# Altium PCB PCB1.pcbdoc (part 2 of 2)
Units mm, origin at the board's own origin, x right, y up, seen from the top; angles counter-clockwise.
Board outline 376.79 x 262.39 mm, 2 copper layers (Top Layer, Bottom Layer), stack 1.58 mm thick; 505 components, 251 nets, 1356 pads, 0 vias.
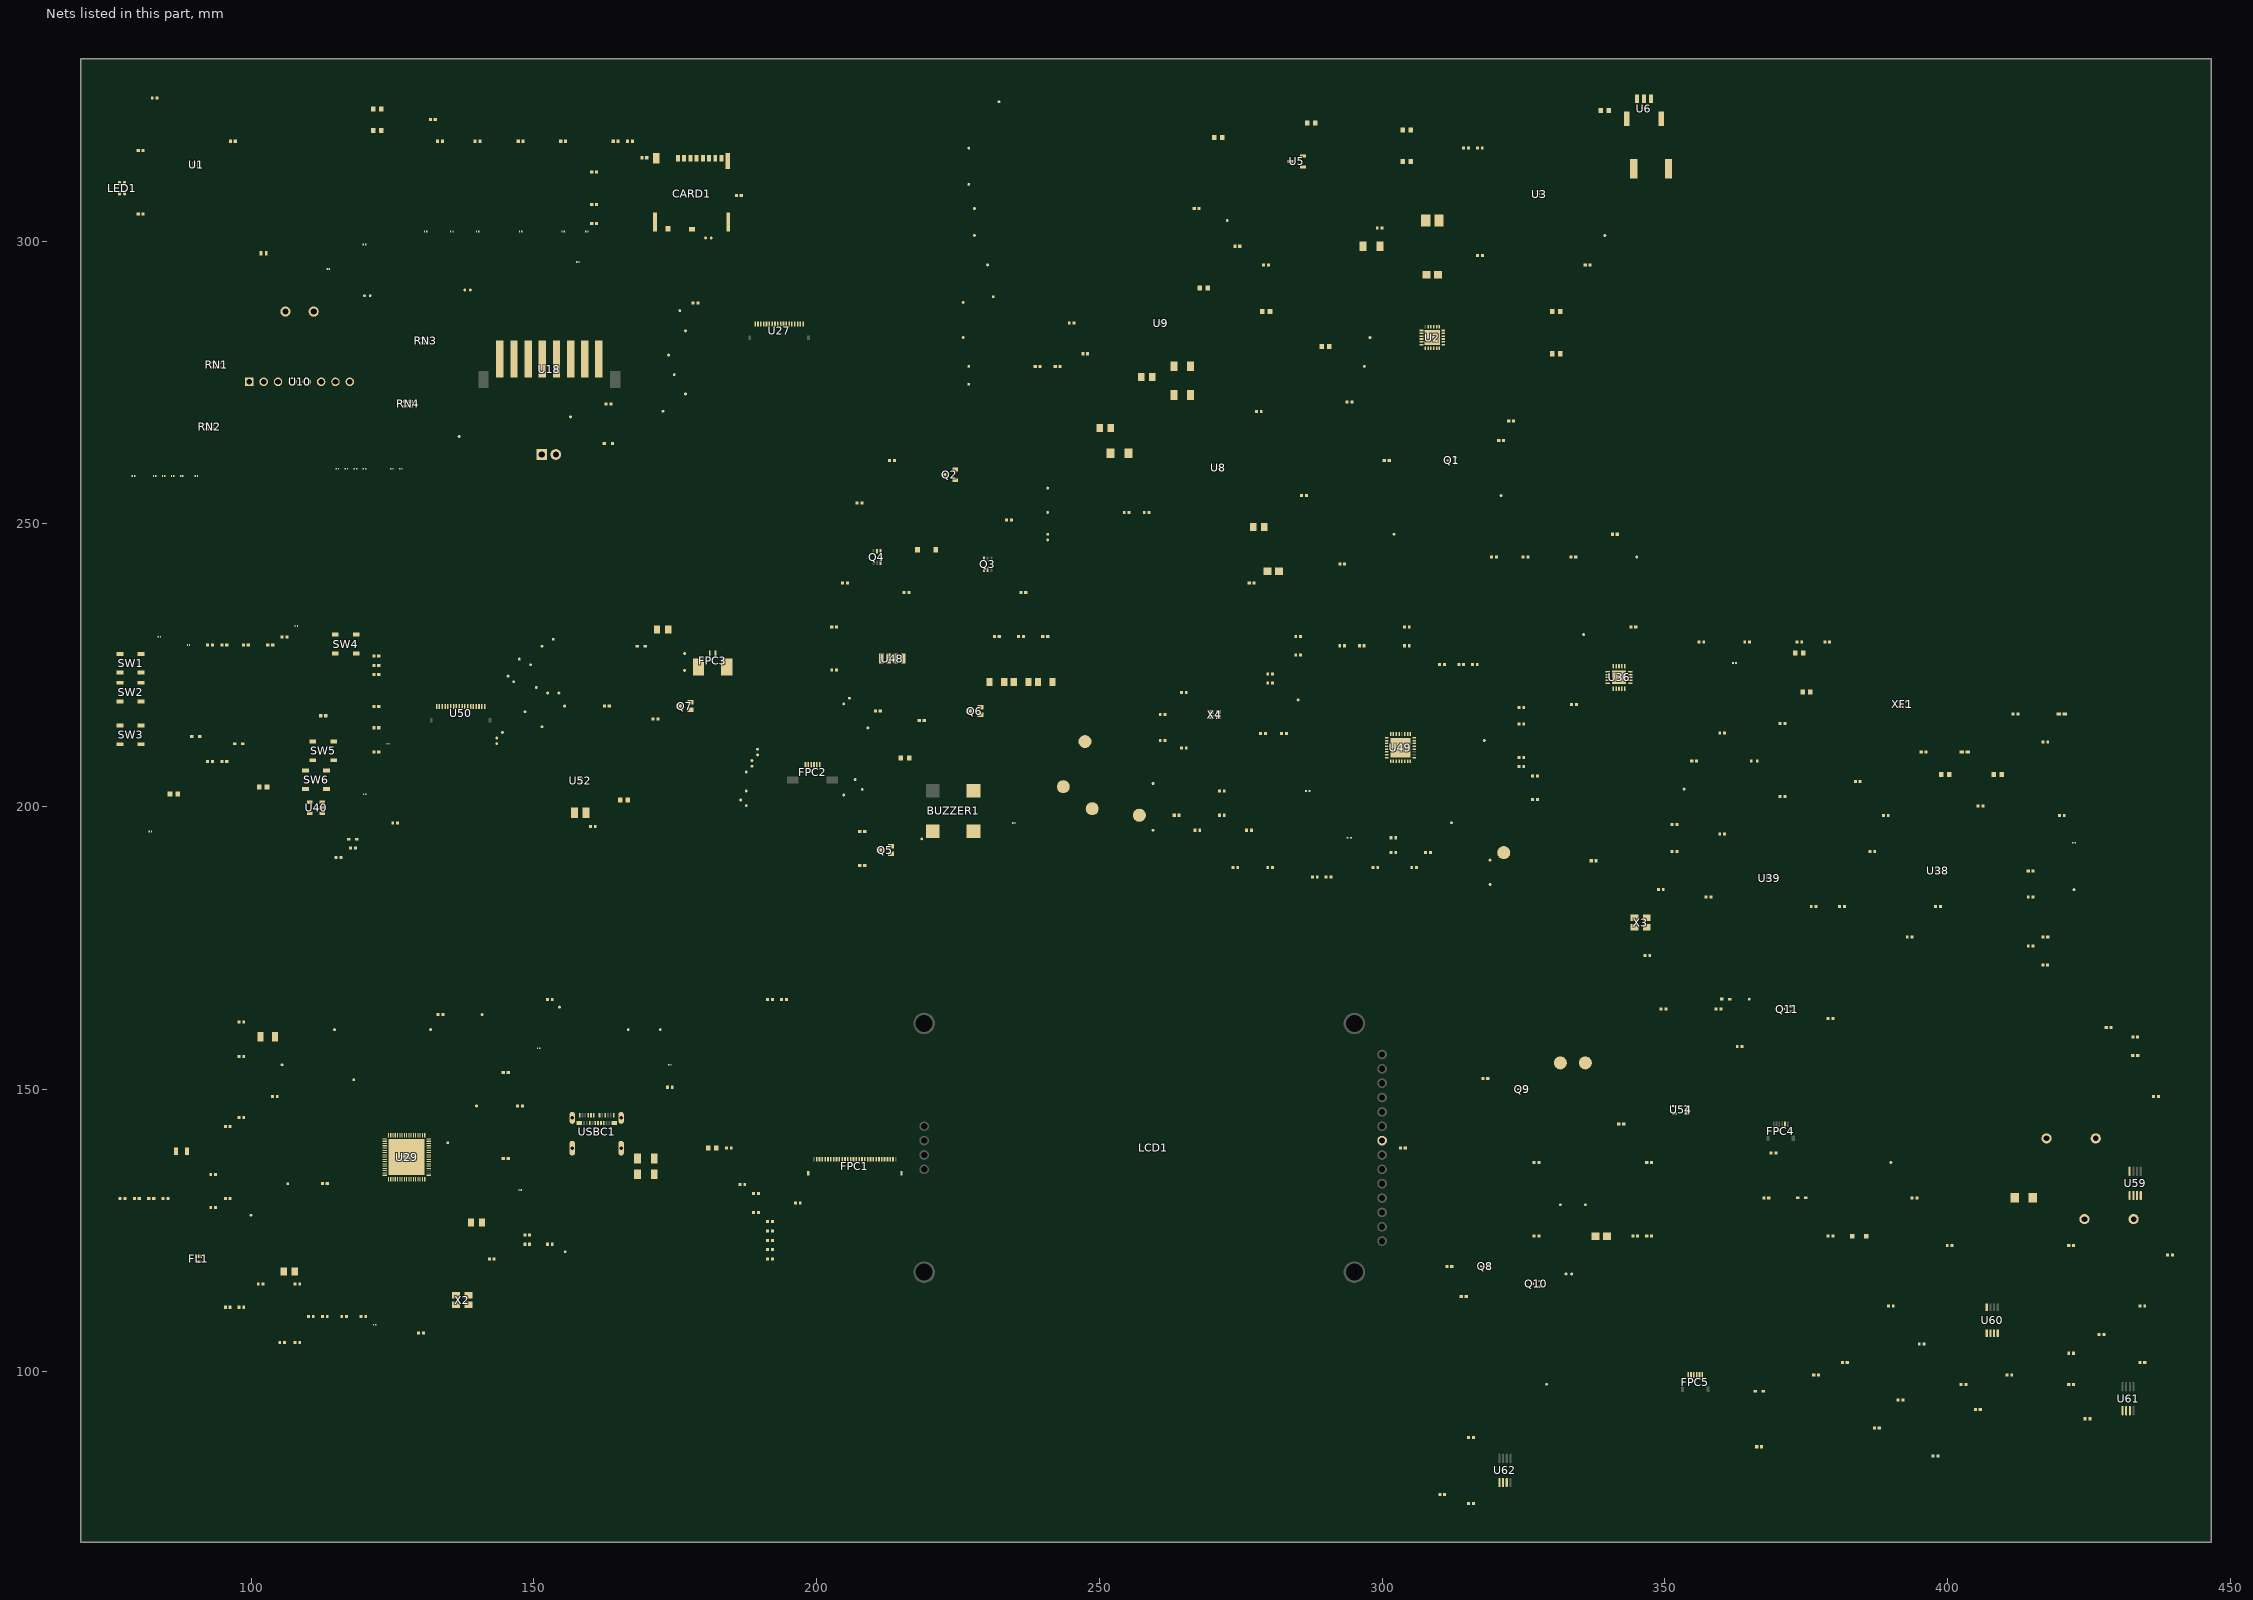
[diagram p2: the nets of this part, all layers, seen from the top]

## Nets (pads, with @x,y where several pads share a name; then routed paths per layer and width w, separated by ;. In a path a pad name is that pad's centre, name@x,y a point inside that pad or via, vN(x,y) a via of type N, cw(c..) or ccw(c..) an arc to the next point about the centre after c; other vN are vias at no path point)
1.65V: R110.1 R111.2 TP64.1 U60.3 U61.3 U62.1 U62.2
3v3: 3v3(2).1 C18.1 C33.1 C34.1 C35.1 C36.2 C37.1 C38.1 C39.1 C42.1 C43.2 C45.2 C46.2 C50.1 C51.2 C61.2 C62.2 C63.1 C64.1 C65.1 C66.1 C82.1 C86.2 C89.1 C122.2 C123.2 FPC1.5 FPC1.6 FPC1.7 FPC1.8 FPC1.9 FPC1.10 FPC1.11 FPC1.12 FPC1.15 R2.2 R3.2 R4.2 R12.1 R13.1 R35.2 R36.2 R39.2 R48.2 R49.2 R61.2 R63.2 R65.1 R69.2 R73.2 R75.2 R101.1 R109.1 SW4.1 SW4.2 SW4.4 TP16.1 TP52.1 TP53.1 U27.3 U29.14 U29.30 U29.33 U29.44 U29.45 U29.55 U29.68 U32.2 U36.4 U36.9 U36.11 U36.14 U36.15 U36.18 U38.7 U39.7 U40.5 U49.1 U50.3
$1N10: R1.1 U2.10
$1N11: PG.1 U2.3
$1N13: STAT.1 U2.4
$1N29: Q1.1 R6.1
$1N34: C2.1 U2.21
$1N35: C2.2 U2.19 U2.20 U4.1
$1N47: R9.2 U3.B1
$1N50: R10.2 U2.22 U7.1
$1N66: C11.1 C12.1 U3.B3
$1N69: GPOUT.1 R12.2 U3.A1
$1N75: L1.2 U8.B2
$1N84: L2.2 R14.1 R15.1
$1N85: C19.2 C20.2 C21.2 L3.2 R14.2 R15.2 U9.A1
$1N86: L3.1 R35.1 R36.1
$1N94: Q2.1 Q3.6 R18.1
$1N123: D7.1 Q3.2 Q4.3 Q4.5 R19.2
$2N2: R29.2 U1.A4
$2N3: R30.2 U1.B4
$2N4: R28.1 U1.C4
$2N5: LED1.1 R28.2
$2N6: LED1.2 R30.1
$2N7: LED1.3 R29.1
$2N16: CARD1.1 R31.1
$2N17: CARD1.8 R32.1
$2N18: C23.2 C24.2 CARD1.4 D5.2 R31.2 R32.2 R33.1 R402.2 R0402.2 R404.2 R406.2
$2N23: CARD1.3 R34.2
$2N25: CARD1.5 R403.2
$2N28: CARD1.7 R405.2
$2N30: CARD1.10 R407.1
$2N31: CARD1.2 R408.2
$2N36: C25.1 F1.1 U10.1
$2N40: RN1.2 U10.2
$2N42: RN1.1 U10.3
$2N44: RN2.4 U10.4
$2N46: RN2.3 U10.5
$2N48: RN2.2 U10.6
$2N50: RN2.1 U10.7
$2N57: RN3.3 U18.2
$2N60: RN3.2 U18.4
$2N62: RN3.1 U18.5 U35.1
$2N64: RN4.4 U18.6 UARTRX.1
$2N66: I2C_SDA.1@156.462,268.906 RN4.3 U18.7
$2N68: I2C_SCL2.1 RN4.2 U18.8
$2N70: RN4.1 U19.1
$2N72: RN4.8 U24.2
$2N88: R23.2 U27.7
$2N95: R24.1 U28.1
$3N6: R37.2 U29.20
$3N41: C27.2 U29.4 X1.2
$3N43: C26.2 U29.3 X1.1
$3N47: U29.35 X2.1
$3N48: U29.34 X2.3
$3N52: L5.1 U29.43
$3N60: R41.1 U29.65
$3N81: C31.1 L4.2 U29.31
$3N85: C32.1 FL1.1 L4.1
$3N96: C40.2 C41.1 U29.13
$3N101: C44.2 L5.2 U29.41
$3N106: R42.1 USBC1.A5
$3N108: R43.1 USBC1.B5
$4N10: C52.1 FPC1.17
$4N12: C53.1 FPC1.18
$4N13: C53.2 C54.2 FPC1.19
$4N14: C54.1 FPC1.20
$4N15: C55.1 FPC1.21
$4N16: C55.2 FPC1.22
$4N17: C56.1 C57.1 C58.1 C59.1 C60.2
$4N18: C56.2 FPC1.23
$4N19: C57.2 FPC1.24
$4N20: C58.2 FPC1.25
$4N21: C59.2 FPC1.26
$4N22: C60.1 FPC1.27
$4N26: LCD1.8 R50.2
$5N8: C67.1 U36.5
$5N10: R51.2 U36.6
$5N13: C68.1 U36.8 X3.1
$5N15: C69.2 U36.10 X3.3
$5N18: C70.1 C71.2 U36.12
$5N20: C70.2 XF1.4
$5N21: C71.1 C72.1 U36.13
$5N22: C72.2 XF1.3
$5N24: R52.1 U36.17
$5N27: L7.1 XF1.1
$5N28: C73.1 L7.2 U37.1
$5N30: C74.2 R53.2 U37.2
$5N36: R54.1 U38.3
$5N37: C75.1 R54.2 R55.2
$5N39: C76.1 L8.2 R55.1
$5N41: L8.1 U39.5
$5N42: R56.1 U38.5
$5N43: C77.1 L9.2 R56.2
$5N45: C78.1 L9.1 R57.1
$5N47: C79.2 L10.2 R57.2
$5N49: L10.1 U39.3
$5N50: R58.1 U38.2
$5N51: C80.1 L11.2 R58.2
$5N53: C81.2 L11.1 U39.2
$5N58: C83.1 L12.2 L13.2 U39.4
$5N61: C84.2 L13.1 R59.1
$5N65: C86.1 U39.6 U39.9
$6N1: R60.1 U40.1
$6N4: R62.1 U40.2
$6N5: D10.1 R62.2 R63.1 R67.1 SW2.4 U41.2
$6N6: C87.2 U41.1
$6N8: C88.2 U42.1
$6N13: U40.4 U43.1
$6N14: R64.2 U43.2
$6N17: D9.1 R60.2 R61.1 R66.1 SW1.4 U42.2
$6N22: D11.2 R68.1 R69.1 SW3.4
$6N25: D12.1 R70.1 R71.1 SW4.3
$6N31: D13.2 R72.1 R73.1 SW5.4
$6N34: D14.2 R74.1 R75.1 SW6.1
$7N2: FPC2.2 R77.2 TP20.1
$7N3: Q5.1 R77.1 R78.2
$7N5: BUZZER1.2 Q5.3 TP21.1
$7N6: BUZZER1.1 R79.1
$7N8: BUZZER1.3 CN1.1 CN2.1 FPC2.3 TP22.1 U44.2
$7N11: FPC2.4 R80.2 TP23.1
$7N12: Q6.1 R80.1 R81.2
$7N14: Q6.3 U45.1 U46.1 U47.1
$7N15: R84.1 U47.2
$7N16: R83.1 U46.2
$7N17: R82.1 U45.2
$7N19: FPC2.5 TP24.1 U48.3
$7N24: C90.1 R76.2 U48.2
$8N2: TP26.1 U49.25
$8N10: TP27.1 U49.2
$8N11: C94.2 U49.4 X4.3
$8N12: C95.2 U49.5 X4.4
$8N17: L14.2 U49.13
$8N18: C96.2 C98.1 C100.2 L14.1
$8N19: C96.1 C97.1 C98.2 C101.1 R85.2
$8N22: L15.1 U49.15
$8N23: C102.1 C103.2 C104.2 L15.2
$8N24: C102.2 C103.1 C105.1 C106.1 R86.1
$8N30: TP32.1 U49.17
$8N31: C108.2 C109.1 U49.24
$8N33: C110.2 C111.2 R87.1 R88.1 U49.9 U49.14
$8N37: C112.2 C113.2 U49.11
$8N44: C118.2 C119.2 U49.7
$8N46: C120.2 C121.2 U49.3
$9N8: R89.1 TP38.1 U50.10
$9N9: Q7.1 R89.2 R90.2
$9N12: FPC3.2 Q7.3 TP39.1 U51.2
$9N14: FPC3.1 R92.1 TP40.1 U51.1
$9N27: U52.B1 U52.B2 U53.2
$10N2: Q8.1 R91.2 R93.2
$10N4: Q8.3 Q9.1 Q10.1 R94.1
$10N7: Q9.2 R95.2
$10N9: Q10.3 R96.1
$10N14: R98.2 R99.2 U54.1
$10N20: R100.2 U55.2
$10N22: C129.2 R102.2 R103.1 R106.1 TP63.1 U55.1 U57.1
$10N24: Q11.3 R103.2
$10N27: R104.1 R105.2 U56.1
$10N28: Q11.1 R104.2
$10N33: FPC5.4 R108.1
$10N36: FPC5.2 U58.1
$10N43: C130.2 C131.1 R106.2
$10N44: C131.2 D15DNP1.1 D15DNP.2 R110.2 U59.3
$10N49: C133.2 R111.1 R112.1 U59.2
$10N53: C133.1 R112.2 R113.2 U59.1
$10N55: C134.1 R113.1 R114.1 R115.2
$10N57: C135.2 R114.2 U60.2
$10N59: C135.1 R115.1 R116.1 U60.1
$10N63: C137.2 R116.2 R117.1 R118.2
$10N65: C138.2 R117.2 U61.2
$10N66: C138.1 R118.1 R119.2 U61.1
$10N68: C139.1 R119.1
$10N71: C140.2 R121.1 R122.2 U62.3
A3V3: C128.2 C132.2 C136.2 D15DNP.1 R121.2 U54.5 U59.8 U60.8
ANTENA_DRAW: C85.2 R59.2 TP18.1
BAT: BAT1.1 BAT2.1 C9.1 R8.2 U3.C1 U3.C3 U6.1
BaTbq-xc6206: C6.2 C7.1 C8.1 U2.13 U2.14 U5.3
BaTbq-xc6207: R8.1 U3.C2
BUTTON_BACK: R66.2 U2.12 U29.2
BUTTON_DOWN: R74.2 U29.50
BUTTON_LEFT: R67.2 U29.29
BUTTON_OK: R70.2 TP11.1 U29.5
BUTTON_RIGHT: R68.2 U29.46
BUTTON_UP: R72.2 U29.28
CC1101_CS: U29.61 U36.7
CC1110_G0: R51.1 U29.16
DISPLAY_CS: FPC1.2 R48.1 U29.59
DISPLAY_DI: FPC1.4 U29.39
DISPLAY_RST: FPC1.3 R49.1 U29.38
"drainosfet e1": Q2.3 R16.1
e24mmd: D7.2 Q4.4 R16.2 R17.1
ext3.3v: C14.2 C15.2 D8.2 EXT3V3(2).1 EXT_3V3.1 L1.1 R27.1 R33.2 U8.A1 U18.1
GND: C1.1 C3.1 C4.1 C5.1 C6.1 C7.2 C8.2 C9.2 C10.1 C11.2 C12.2 C14.1 C15.1 C18.2 C19.1 C20.1 C22.2 C23.1 C24.1 C25.2 C26.1 C27.1 C28.1 C29.1 C30.2 C31.2 C32.2 C33.2 C34.2 C35.2 C36.1 C37.2 C38.2 C39.2 C40.1 C41.2 C42.2 C43.1 C44.1 C45.1 C46.1 C47.1 C48.1 C48.2 C49.1 C49.2 C50.2 C51.1 C52.2 C61.1 C62.1 C63.2 C64.2 C65.2 C66.2 C67.2 C68.2 C69.1 C73.2 C74.1 C75.2 C76.2 C77.2 C78.2 C79.1 C80.2 C81.1 C82.2 C83.2 C84.1 C85.1 C87.1 C88.1 C89.2 C90.2 C91.1 C92.1 C93.1 C94.1 C95.1 C99.2 C100.1 C101.2 C104.1 C105.2 C107.2 C108.1 C109.2 C110.1 C111.1 C112.1 C113.1 C114.1 C115.1 C116.1 C117.1 C118.1 C119.1 C120.1 C121.1 C122.1 C123.1 C124.1 C125.1 C126.1 C126.2 C127.1 C127.2 C128.1 C130.1 C132.1 C134.2 C136.1 C137.1 C139.2 C140.1 CARD1.6 CARD1.9 CARD1.11 CN3.1 CN4.1 CN5.1 CN6.1 CN7.1 D1.1 D2.1 D3.1 D4.1 D5.1 D6.1 D8.1 D9.2 D10.2 D11.1 D12.2 D13.1 D14.1 D15DNP1.2 FL1.2 FL1.3 FL1.5 FPC1.16 FPC1.28 FPC1.29 FPC1.31 FPC1.32 FPC2.6 FPC3.3 FPC3.4 FPC5.1 GND1.1 GND2.1 GND3.1 GND4.1 L6.1 L6.2 L12.1 Q1.2 Q5.2 Q6.2 Q7.2 Q8.2 Q10.2 Q11.2 R1.2 R7.2 R9.1 R11.1 R18.2 R19.1 R20.2 R21.1 R22.2 R42.2 R43.2 R44.1 R44.2 R45.1 R45.2 R46.1 R46.2 R47.1 R47.2 R52.2 R53.1 R71.2 R78.1 R81.1 R85.1 R86.2 R87.2 R88.2 R90.1 R93.1 R95.1 R96.2 R97.1 R97.2 R98.1 R100.1 R102.1 R120.1 R120.2 R122.1 SW1.1 SW1.2 SW1.3 SW2.1 SW2.2 SW2.3 SW3.1 SW3.2 SW3.3 SW5.1 SW5.2 SW5.3 SW6.2 SW6.3 SW6.4 TP1.1 TP15.1 TP17.1 TP25.1 TP28.1 TP29.1 TP30.1 TP31.1 TP34.1 TP35.1 TP50.1 TP51.1 TP58.1 TP59.1 TP60.1 TP61.1 U1.A3 U1.B1 U1.B2 U1.B3 U2.2 U2.9 U2.17 U2.18 U2.25 U3.B2 U5.1 U6.3 U6.4 U6.5 U7.2 U10.8 U11.1 U12.1 U13.1 U14.1 U15.1 U16.1 U17.1 U18.3 U19.2 U20.1 U21.1 U22.1 U23.1 U24.1 U25.1 U26.2 U27.5 U27.17 U27.18 U29.26 U29.32 U29.42 U29.69 U30.1 U31.2 U32.1 U33.1 U34.1 U34.2 U36.16 U36.19 U36.21 U38.4 U38.6 U38.9 U40.3 U44.1 U48.1 U48.4 U49.6 U49.12 U49.16 U49.20 U49.21 U49.26 U49.33 U50.5 U50.6 U50.8 U52.C1 U52.C2 U52.C3 U54.2 U54.3 U57.2 U59.4 U60.4 USBC1.0 USBC1.A1 USBC1.A12 USBC1.B1 USBC1.B12 X2.2 X2.4 X3.2 X3.4 X4.1 X4.2 XF1.2
I2C_SCL: R4.1 R25.1 R25.2 U1.C2 U2.5 U3.A3 U29.24
I2C_SDA: I2C_SDA.1@345.048,244.129 R3.1 U1.C1 U2.6 U3.A2 U29.51
iBTN: C129.1 R24.2 R107.1 R108.2 TP45.1 U27.12 U29.48 U50.14
IR_RX: R109.2 TP48.1 U27.15 U29.15 U50.17 U58.2
IR_TX: FPC5.3 IR_TX.1 TP47.1 U27.14 U29.7 U50.16
LCD_LED: U1.A1
LDO_3.3V: C10.2 LDO1.1 LDO2.1 U5.2 U29.1
NET1_N: D-.1 R38.1 U29.52
NET1_P: R39.1 R40.2 TP5.1 U29.53
NET2_N: R38.2 U30.2 USBC1.A7 USBC1.B7
NET2_P: R40.1 U31.1 USBC1.A6 USBC1.B6
NFC_CS: NFC_CS.1 TP33.1 U27.4 U29.40 U49.29 U50.4
NFC_IRQ: TP62.1 U49.27 U56.2
OTG: OTG.1 Q1.3 R5.2 U2.8
PA4: RN2.5 U13.2 U29.19
PA6: RN1.8 U12.2 U29.21
PA7: RN1.7 U17.2 U29.22
PB2: RN2.7 U15.2 U29.27
PB3: RN2.6 U14.2 U29.63
PC0: RN4.7 U23.2 U29.9
PC1: RN4.6 U20.2 U29.10
PC3: RN2.8 U16.2 U29.12
PERIPH_POWER: R13.2 U8.C1 U29.18
PGND: C17.1 C21.1 R21.2 U9.C2
PGND2: C13.1 C16.2 R22.1 U8.C2
PWR_INT: PWR_INT.1 R2.1 U2.7
REGN: R20.1 R26.1 TEMP.1 U6.2
RESET: C30.1 R64.1 R65.2 TP12.1 U1.C3 U29.8
RF_SW_0: U29.25 U38.8 U39.1
RF_SW_1: U36.3 U38.1 U39.8
RFI_N: C106.2 C107.1 U49.23
RFI_P: C97.2 C99.1 U49.22
RFID__CARRED: FPC4.2 R99.1 R101.2 TP4.1 TP49.1 U27.16 U29.57 U50.18 U54.4
RFID_OUT: R91.1 TP2.1 TP42.1 U27.10 U29.47 U50.12
RFID_PULL: R105.1 RFID_PULL.1 TP41.1 TP44.1 U27.9 U29.17 U50.11
SD_CD: D6.2 R406.1 R407.2 U29.58
SD_CS: D1.2 R408.1 U29.60
SPEAKER: FPC5.5 TP3.1 TP46.1 U27.13 U29.6 U50.15
SPI_D_MISO: D4.2 R404.1 R405.1 TP6.1 U29.11
SPI_D_MOSI: C28.2 D2.2 FPC1.14 R34.1 R0402.1 TP9.1 U29.49
SPI_D_SCK: C29.2 D3.2 FPC1.13 R402.1 R403.1 TP10.1 U29.62
SPI_R_MISO: C93.2 R23.1 TP7.1 TP37.1 U29.64 U36.2 U49.32 U50.9
SPI_R_MOSI: C92.2 R41.2 TP8.1 TP43.1 U36.20 U49.31 U50.13
SPI_R_SCK: C91.2 R37.1 R_CLK.1 TP36.1 U27.6 U36.1 U49.30 U50.7
ST25_R_MOSI: U27.11
swclk: RN3.6 SWCLK.1 U26.1
SWCLK: U29.56
swdcdc: C16.1 R27.2
SWDcDc2: L2.1 U9.B2
swdio: RN3.7 SWDIO.1 U25.2
SWDIO: U29.54
SYS: C4.2 C5.2 C13.2 C17.2 C22.1 C125.2 FPC2.1 FPC5.6 LED1.4 R5.1 R50.1 R76.1 R79.2 R82.2 R83.2 R84.2 R92.2 SYS1.1 SYS2.1 TP19.1 TP56.1 TP57.1 U1.A2 U2.15 U2.16 U4.2 U8.A2 U8.B1 U9.A2 U9.B1 U9.C1 U27.1 U27.2 U50.1 U50.2 U52.A3 U52.B3 U53.1
TS: R10.1 R11.2 R26.2 U2.11
UART_RX: RN4.5 U21.2 U29.67
UART_TX: RN3.8 U22.2 U29.66
usb5v: C1.2 C114.2 C115.2 C116.2 C117.2 C124.2 F1.2 Q2.2 Q3.1 Q9.3 R94.2 R107.2 TP54.1 TP55.1 U2.1 U11.2 U28.2 U49.8 U49.10 U52.A1 U52.A2 USB5V(1).1 USB5V(2).1
VBUS: C47.2 R6.2 R7.1 R17.2 TP13.1 TP14.1 U33.2 USBC1.A4 USBC1.A9 USBC1.B4 USBC1.B9
vbus-pmid: C3.2 U2.23
VIBRO: U27.8 U29.23 VIBRO.1
pads on no net: BUZZER1.4 FL1.4 FL1.6 FPC1.1 FPC1.30 FPC2.7 FPC2.8 FPC4.1 FPC4.3 FPC4.4 FPC4.5 FPC4.6 FPC4.7 FPC4.8 FPC5.7 FPC5.8 LCD1.0 LCD1.1 LCD1.2 LCD1.3 LCD1.4 LCD1.5 LCD1.6 LCD1.7 LCD1.9 LCD1.10 LCD1.11 LCD1.12 LCD1.13 LCD1.14 LCD1.15 LCD1.16 LCD1.17 LCD1.18 Q3.3 Q3.4 Q3.5 Q4.1 Q4.2 Q4.6 RN1.3 RN1.4 RN1.5 RN1.6 RN3.4 RN3.5 U2.24 U18.9 U18.10 U27.19 U27.20 U29.36 U29.37 U49.18 U49.19 U49.28 U50.19 U50.20 U59.5 U59.6 U59.7 U60.5 U60.6 U60.7 U61.4 U61.5 U61.6 U61.7 U61.8 U62.4 U62.5 U62.6 U62.7 U62.8 USBC1.A2 USBC1.A3 USBC1.A8 USBC1.A10 USBC1.A11 USBC1.B2 USBC1.B3 USBC1.B8 USBC1.B10 USBC1.B11 XF1.5 XF1.6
